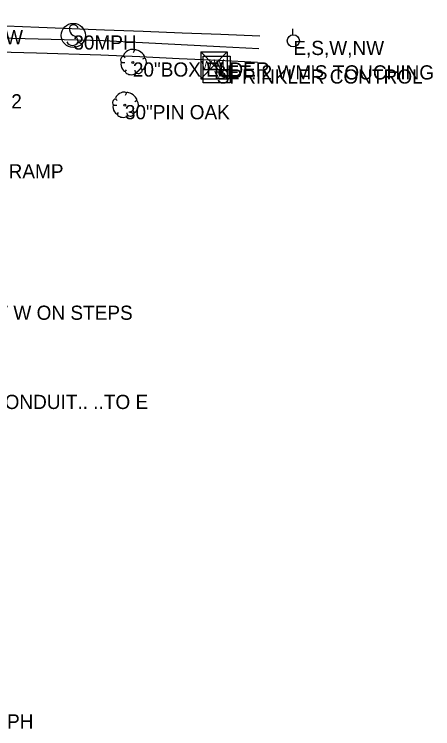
# Model space of a CAD drawing. Extents: x 997398 to 1003416, y 334596 to 337085.
# Drawn here: x 999393.6 to 999540.7, y 335017.8 to 335269.3 of the extents above; entities that cross this region are included whole.
import ezdxf

# ---------------------------------------------------------------- set-up
doc = ezdxf.new("R2010")
doc.units = 0
for name, color, linetype in [('S_BUILDING_ANNOT', 7, 'Continuous'), ('S_CURB', 7, 'Continuous'), ('S_PRIMARY_CTL_ANNOT', 7, 'Continuous'), ('S_SECONDARY_CTL_ANNOT', 7, 'Continuous'), ('S_SIDEWALK', 7, 'Continuous'), ('S_SIGN', 7, 'Continuous'), ('S_SIGN_ANNOT', 7, 'Continuous'), ('S_TREE', 7, 'Continuous'), ('S_TREE_ANNOT', 7, 'Continuous'), ('S_UTILITY_POLE', 7, 'Continuous'), ('S_UTILITY_POLE_ANNOT', 7, 'Continuous'), ('S_WATER_UTILITIES', 7, 'Continuous'), ('S_WATER_UTILITIES_ANNOT', 7, 'Continuous')]:
    doc.layers.add(name, color=color, linetype=linetype)

msp = doc.modelspace()

# ---------------------------------------------------------------- linework, layer by layer
at = {"layer": 'S_CURB'}
msp.add_lwpolyline([(999479.94, 335261.63), (999466.28, 335262.15), (999452.62, 335262.68), (999438.96, 335263.21), (999425.29, 335263.73), (999402.2, 335264.66), (999379.11, 335265.58), (999364.38, 335266.17), (999349.65, 335266.76), (999345.81, 335266.95), (999330.22, 335267.52), (999314.63, 335268.09), (999310.32, 335268.23), (999297.87, 335268.66), (999282.9, 335269.18), (999277.69, 335269.31), (999272.89, 335268.92), (999266.95, 335267.42), (999261.74, 335264.66)], dxfattribs=at)
at = {"layer": 'S_SIDEWALK'}
for points in [[(999479.54, 335257.17), (999465.91, 335257.86), (999452.28, 335258.55), (999438.64, 335259.23), (999425.01, 335259.92), (999401.97, 335260.55), (999378.93, 335261.19), (999365.95, 335261.49), (999352.97, 335261.78), (999352.89, 335261.13), (999340.29, 335261.71), (999345.53, 335266.72)], [(999479.13, 335252.32), (999465.35, 335252.98), (999451.57, 335253.65), (999437.79, 335254.31), (999424.01, 335254.97), (999401.43, 335255.6), (999378.85, 335256.22), (999365.86, 335256.64), (999352.87, 335257.07), (999338.02, 335257.84), (999337.27, 335257.09), (999324.82, 335257.13), (999323.89, 335258.38), (999308.61, 335258.94), (999296.79, 335259.38), (999277.61, 335260.14), (999273.31, 335259.2), (999268.8, 335256.09), (999265.61, 335252.19), (999261.19, 335243.68)]]:
    msp.add_lwpolyline(points, dxfattribs=at)
at = {"layer": 'S_SIGN'}
msp.add_circle((999414.33, 335261.87), 4.24, dxfattribs=at)
for centre, radius, start, end in [((999415.5, 335264.12), 2.55, 167.1196, 241.9813), ((999414.46, 335264.02), 1.62, 16.5258, 156.8957), ((999413.63, 335259.58), 2.38, 358.6529, 73.7063), ((999414.07, 335260.47), 2.17, 204.641, 335.359)]:
    msp.add_arc(centre, radius, start, end, dxfattribs=at)
at = {"layer": 'S_TREE'}
for p, q in [((999435.83, 335256.62), (999435.44, 335255.76)), ((999432.03, 335254.6), (999432.53, 335254.02)), ((999431.37, 335252.28), (999432.49, 335252.28)), ((999439.39, 335253.83), (999438.73, 335253.56)), ((999432.53, 335249.1), (999433, 335249.8)), ((999436.21, 335248.83), (999436.14, 335249.6)), ((999438.62, 335249.72), (999438.15, 335250.15)), ((999433.02, 335241.6), (999432.63, 335240.74)), ((999429.22, 335239.58), (999429.73, 335239)), ((999428.56, 335237.26), (999429.69, 335237.26)), ((999436.58, 335238.81), (999435.93, 335238.54)), ((999429.73, 335234.08), (999430.19, 335234.78)), ((999433.41, 335233.81), (999433.33, 335234.58)), ((999435.81, 335234.7), (999435.34, 335235.13))]:
    msp.add_line(p, q, dxfattribs=at)
for centre in [(999435.27, 335252.37), (999432.46, 335237.35)]:
    msp.add_circle(centre, 0.341, dxfattribs=at)
for centre, major_axis, ratio, start_param, end_param in [((999433.93, 335255.57), (1.86, 1.08), 0.471018, 0, 3.141593), ((999437.59, 335255.25), (-1.81, 1.36), 0.405113, 3.141593, 6.283186), ((999431.7, 335253.46), (0.31, 1.03), 0.646762, 0, 3.141593), ((999432, 335250.81), (-0.61, 1.6), 0.420543, 6.283185, 9.424777), ((999438.94, 335251.84), (0.46, 2.04), 0.482994, 3.141593, 6.283185), ((999434.46, 335249.03), (-1.83, 0.19), 0.529943, 0, 3.141593), ((999437.42, 335249.32), (1.09, 0.46), 0.711534, 3.141592, 6.283185), ((999431.13, 335240.55), (1.86, 1.08), 0.471018, 0, 3.141593), ((999434.78, 335240.23), (-1.81, 1.36), 0.405113, 3.141593, 6.283186), ((999428.89, 335238.44), (0.31, 1.03), 0.646762, 0, 3.141593), ((999429.2, 335235.79), (-0.61, 1.6), 0.420543, 6.283185, 9.424777), ((999436.14, 335236.82), (0.46, 2.04), 0.482994, 3.141593, 6.283185), ((999431.66, 335234.01), (-1.83, 0.19), 0.529943, 0, 3.141593), ((999434.61, 335234.3), (1.09, 0.46), 0.711534, 3.141592, 6.283185)]:
    msp.add_ellipse(centre, major_axis=major_axis, ratio=ratio, start_param=start_param, end_param=end_param, dxfattribs=at)
at = {"layer": 'S_UTILITY_POLE'}
msp.add_line((999491.59, 335262.1), (999491.59, 335264.21), dxfattribs=at)
msp.add_circle((999491.72, 335259.96), 2.13, dxfattribs=at)
at = {"layer": 'S_WATER_UTILITIES'}
for p, q in [((999459.15, 335256.1), (999468.49, 335256.1)), ((999459.15, 335256.1), (999459.15, 335246.61)), ((999459.15, 335256.1), (999468.49, 335246.61)), ((999468.49, 335256.1), (999459.15, 335246.61)), ((999460.07, 335254.6), (999469.49, 335254.6)), ((999460.07, 335245.18), (999460.07, 335254.6)), ((999468.49, 335256.1), (999468.49, 335246.61)), ((999469.49, 335254.6), (999469.49, 335245.18)), ((999460.07, 335249.91), (999469.49, 335249.91)), ((999459.15, 335246.61), (999468.49, 335246.61)), ((999469.49, 335245.18), (999460.07, 335245.18))]:
    msp.add_line(p, q, dxfattribs=at)

# ---------------------------------------------------------------- texts
at = {"layer": 'S_BUILDING_ANNOT'}
for s, p in [('CHURCH,CONT.S.,ON RAMP', (999319.89, 335211.53)), ('AT ROOFLINE,CONT W ON STEPS', (999326.01, 335161.74))]:
    msp.add_text(s, height=5, dxfattribs=at).set_placement(p)
at = {"layer": 'S_PRIMARY_CTL_ANNOT'}
msp.add_text('PD:AHTD STD. MON. STAMPED PN 2', height=5, dxfattribs=at).set_placement((999279.57, 335236.17))
at = {"layer": 'S_SECONDARY_CTL_ANNOT'}
msp.add_text('PD:MAG NAIL IN ASPH', height=5, dxfattribs=at).set_placement((999328.62, 335017.86))
at = {"layer": 'S_SIGN_ANNOT'}
msp.add_text('30MPH', height=5, dxfattribs=at).set_placement((999414.33, 335256.87))
at = {"layer": 'S_TREE_ANNOT'}
for s, p in [('20"BOX ELDER', (999435.27, 335247.37)), ('30"PIN OAK', (999432.46, 335232.35))]:
    msp.add_text(s, height=5, dxfattribs=at).set_placement(p)
at = {"layer": 'S_UTILITY_POLE_ANNOT'}
for s, p in [('E,W,SKIP W', (999358.75, 335258.74)), ('E,S,W,NW', (999491.72, 335254.96)), ('OHE FROM WSW,3"CONDUIT.. ..TO E', (999322.41, 335130.34))]:
    msp.add_text(s, height=5, dxfattribs=at).set_placement(p)
at = {"layer": 'S_WATER_UTILITIES'}
for s, p in [('W M', (999459.36, 335249.87)), ('W', (999463.62, 335250.44)), ('V', (999463.86, 335246.38))]:
    msp.add_text(s, height=3, rotation=360, dxfattribs=at).set_placement(p)
at = {"layer": 'S_WATER_UTILITIES_ANNOT'}
for s, p in [("BET. 2 WM'S TOUCHING", (999463.82, 335246.35)), ('SPRINKLER CONTROL', (999464.78, 335244.91))]:
    msp.add_text(s, height=5, dxfattribs=at).set_placement(p)

doc.saveas('drawing.dxf')
